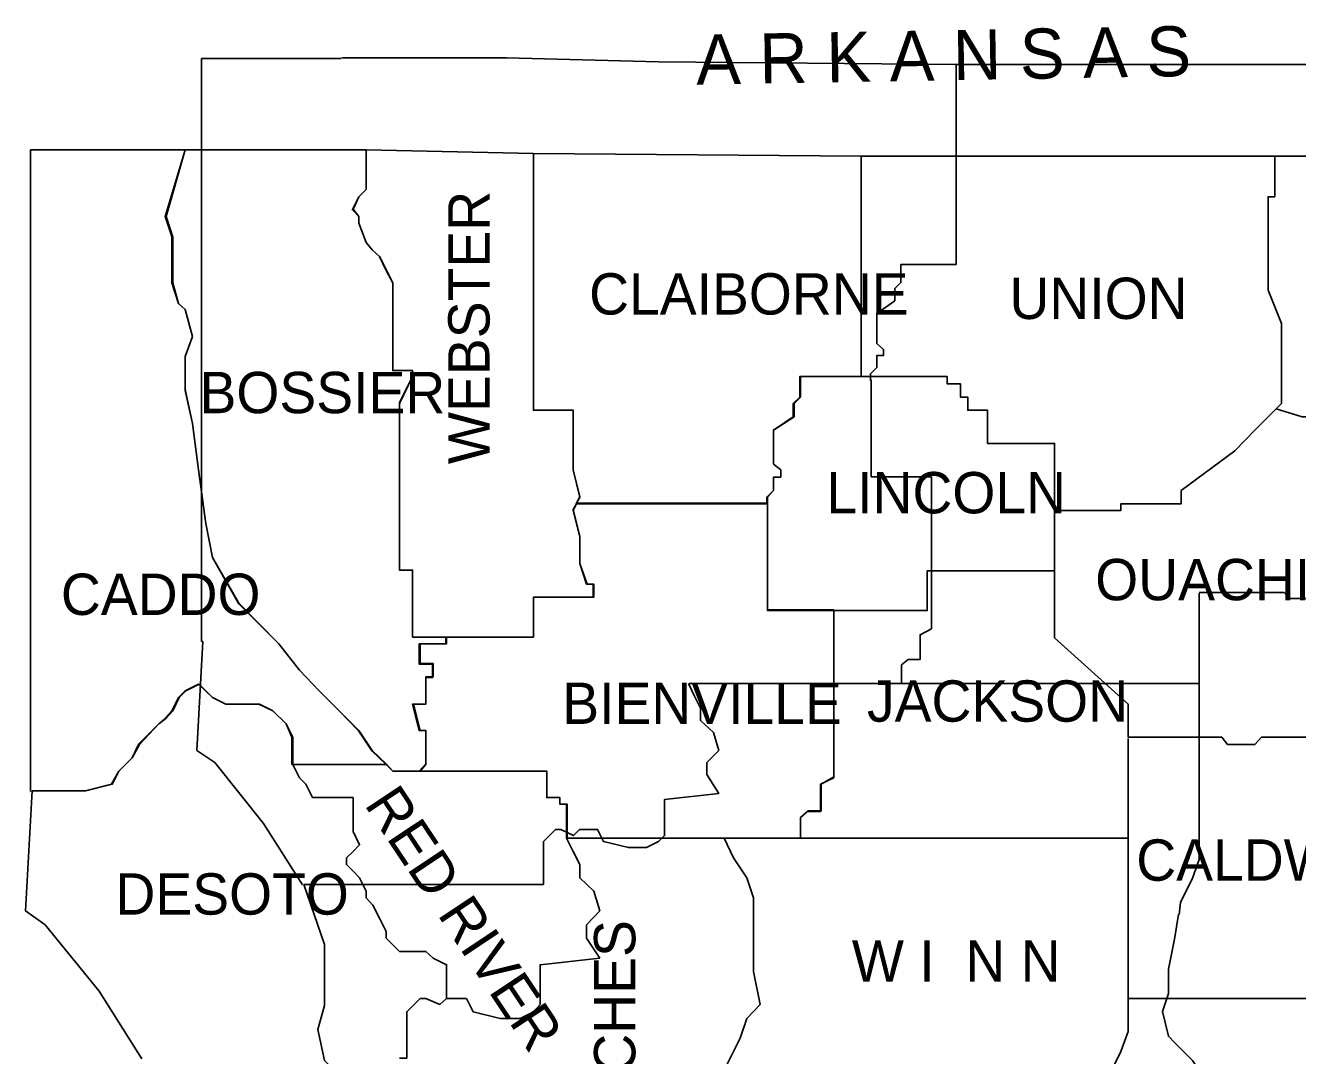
# Model space of a CAD drawing. Extents: x 0.19 to 2.82, y 0.04 to 1.79.
# Drawn here: x 2.194 to 2.3524, y 1.6264 to 1.7547 of the extents above; entities that cross this region are included whole.
import ezdxf

# ---------------------------------------------------------------- set-up
doc = ezdxf.new("R2010")
doc.units = 0
for name, color, linetype in [('Dist04', 7, 'Continuous'), ('Dist05', 7, 'Continuous'), ('Dist08', 7, 'Continuous'), ('Dist58', 7, 'Continuous'), ('Standard Info', 7, 'Continuous')]:
    doc.layers.add(name, color=color, linetype=linetype)

msp = doc.modelspace()

# ---------------------------------------------------------------- linework, layer by layer
at = {"layer": 'Dist04'}
for p, q in [((2.2159, 1.678), (2.2159, 1.75058)), ((2.2159, 1.75058), (2.23332, 1.75058)), ((2.2334, 1.75067), (2.2539, 1.75067)), ((2.2539, 1.75067), (2.27282, 1.75017)), ((2.27282, 1.75017), (2.3099, 1.74983)), ((2.21532, 1.66442), (2.21607, 1.678)), ((2.21607, 1.678), (2.2159, 1.678))]:
    msp.add_line(p, q, dxfattribs=at)
for points in [[(2.3099, 1.74983), (2.3099, 1.72492)], [(2.3099, 1.72492), (2.30299, 1.72492), (2.30299, 1.72267), (2.30224, 1.72192), (2.30224, 1.72042), (2.29999, 1.71883), (2.29999, 1.71508), (2.30082, 1.71433), (2.30082, 1.71358), (2.29999, 1.71358), (2.29999, 1.71208), (2.29924, 1.71133), (2.29924, 1.7105)], [(2.29932, 1.71058), (2.29932, 1.6985), (2.30682, 1.6985)], [(2.30682, 1.6985), (2.30682, 1.67958), (2.3054, 1.67883), (2.3054, 1.6765), (2.3054, 1.67575), (2.3039, 1.67575), (2.30307, 1.67508), (2.30307, 1.67275)], [(2.27657, 1.67275), (2.27732, 1.67117), (2.27807, 1.66967), (2.27807, 1.66817), (2.27965, 1.66667), (2.28032, 1.66442), (2.27882, 1.66292), (2.27882, 1.66142), (2.28032, 1.65908), (2.27357, 1.65833), (2.27357, 1.65383), (2.27282, 1.65308), (2.27132, 1.65233), (2.26907, 1.65233), (2.26599, 1.65308), (2.26524, 1.65458), (2.26299, 1.65458)], [(2.30307, 1.67275), (2.27665, 1.67275)], [(2.22849, 1.64767), (2.22365, 1.65533), (2.21757, 1.66292), (2.21532, 1.66442)], [(2.26299, 1.65458), (2.26224, 1.65383), (2.26065, 1.65458), (2.25999, 1.65458), (2.25849, 1.65308), (2.25849, 1.64775), (2.25765, 1.64775)], [(2.25765, 1.64775), (2.22865, 1.64775)]]:
    msp.add_lwpolyline(points, dxfattribs=at)
at = {"layer": 'Dist05'}
msp.add_line((2.3099, 1.74983), (2.35674, 1.74983), dxfattribs=at)
for points in [[(2.3099, 1.72492), (2.3099, 1.74983)], [(2.29924, 1.7105), (2.29924, 1.71133), (2.29999, 1.71208), (2.29999, 1.71358), (2.30082, 1.71358), (2.30082, 1.71433), (2.29999, 1.71508), (2.29999, 1.71883), (2.30224, 1.72042), (2.30224, 1.72192), (2.30299, 1.72267), (2.30299, 1.72492), (2.3099, 1.72492)], [(2.30682, 1.6985), (2.29932, 1.6985), (2.29932, 1.71058)], [(2.30307, 1.67275), (2.30307, 1.67508), (2.3039, 1.67575), (2.3054, 1.67575), (2.3054, 1.6765), (2.3054, 1.67883), (2.30682, 1.67958), (2.30682, 1.6985)], [(2.36049, 1.68408), (2.35524, 1.68408), (2.35449, 1.68333), (2.3514, 1.68333), (2.35074, 1.68408), (2.34015, 1.68408)], [(2.34015, 1.684), (2.34015, 1.67275)], [(2.34015, 1.67275), (2.30307, 1.67275)]]:
    msp.add_lwpolyline(points, dxfattribs=at)
at = {"layer": 'Dist08'}
for points in [[(2.27657, 1.67275), (2.27732, 1.67117), (2.27807, 1.66967), (2.27807, 1.66817), (2.27965, 1.66667), (2.28032, 1.66442), (2.27882, 1.66292), (2.27882, 1.66142), (2.28032, 1.65908), (2.27357, 1.65833), (2.27357, 1.65383), (2.27282, 1.65308), (2.27132, 1.65233), (2.26907, 1.65233), (2.26599, 1.65308), (2.26524, 1.65458), (2.26299, 1.65458)], [(2.30307, 1.67275), (2.27665, 1.67275)], [(2.34015, 1.67275), (2.30307, 1.67275)], [(2.34015, 1.65458), (2.34015, 1.67275)], [(2.26299, 1.65458), (2.26224, 1.65383), (2.26065, 1.65458), (2.25999, 1.65458), (2.25849, 1.65308), (2.25849, 1.64775), (2.25765, 1.64775)], [(2.33765, 1.644), (2.33782, 1.6455), (2.33932, 1.6485), (2.34015, 1.65083), (2.34015, 1.65458)], [(2.22865, 1.64775), (2.23124, 1.64025), (2.23124, 1.63267), (2.2304, 1.62967), (2.23124, 1.62583), (2.23199, 1.62508), (2.23649, 1.62283), (2.23882, 1.61675), (2.24032, 1.61375), (2.24182, 1.61), (2.24182, 1.60542), (2.24257, 1.60317), (2.24482, 1.60008), (2.24782, 1.59633), (2.24957, 1.59408)], [(2.25765, 1.64775), (2.22865, 1.64775)], [(2.36207, 1.60008), (2.36132, 1.60167), (2.35982, 1.60392), (2.35749, 1.60542), (2.35524, 1.60617), (2.35299, 1.6085), (2.3514, 1.61225), (2.3499, 1.61525), (2.3469, 1.61675), (2.3439, 1.61908), (2.34165, 1.62133), (2.34082, 1.62358), (2.33932, 1.62583), (2.33707, 1.62808), (2.33632, 1.62883), (2.33557, 1.63192), (2.33632, 1.63417), (2.33632, 1.63717), (2.33707, 1.64092), (2.33757, 1.644)]]:
    msp.add_lwpolyline(points, dxfattribs=at)
at = {"layer": 'Dist58'}
for points in [[(2.34015, 1.68408), (2.35074, 1.68408), (2.3514, 1.68333), (2.35449, 1.68333), (2.35524, 1.68408), (2.36049, 1.68408)], [(2.34015, 1.67275), (2.34015, 1.684)], [(2.34015, 1.65458), (2.34015, 1.67275)], [(2.33765, 1.644), (2.33782, 1.6455), (2.33932, 1.6485), (2.34015, 1.65083), (2.34015, 1.65458)], [(2.36207, 1.60008), (2.36132, 1.60167), (2.35982, 1.60392), (2.35749, 1.60542), (2.35524, 1.60617), (2.35299, 1.6085), (2.3514, 1.61225), (2.3499, 1.61525), (2.3469, 1.61675), (2.3439, 1.61908), (2.34165, 1.62133), (2.34082, 1.62358), (2.33932, 1.62583), (2.33707, 1.62808), (2.33632, 1.62883), (2.33557, 1.63192), (2.33632, 1.63417), (2.33632, 1.63717), (2.33707, 1.64092), (2.33757, 1.644)]]:
    msp.add_lwpolyline(points, dxfattribs=at)
at = {"layer": 'Standard Info'}
for p, q in [((2.19464, 1.65929), (2.19464, 1.73922)), ((2.19464, 1.73922), (2.2138, 1.73922)), ((2.2138, 1.73922), (2.21389, 1.73922)), ((2.21389, 1.73922), (2.23644, 1.73922)), ((2.23644, 1.73922), (2.25725, 1.73876)), ((2.25725, 1.73876), (2.29804, 1.7384)), ((2.29804, 1.7384), (2.34955, 1.7384)), ((2.34955, 1.7384), (2.39951, 1.7384)), ((2.34974, 1.70696), (2.35038, 1.7076)), ((2.2622, 1.6944), (2.26265, 1.69522)), ((2.24634, 1.67854), (2.24221, 1.67854)), ((2.22727, 1.66268), (2.23891, 1.66268)), ((2.23974, 1.66186), (2.23891, 1.66277)), ((2.24304, 1.66186), (2.23974, 1.66186)), ((2.194, 1.64444), (2.19482, 1.65938))]:
    msp.add_line(p, q, dxfattribs=at)
for points in [[(2.21389, 1.73922), (2.21141, 1.73088), (2.21224, 1.72841), (2.21224, 1.72511), (2.21224, 1.72263), (2.21306, 1.72006), (2.21389, 1.71933), (2.2148, 1.71594), (2.21389, 1.71346), (2.21389, 1.70925), (2.2148, 1.70512), (2.21554, 1.69935), (2.21645, 1.69266), (2.21728, 1.68844), (2.22058, 1.68266), (2.22553, 1.67771), (2.2281, 1.67441), (2.23057, 1.67185), (2.23305, 1.66937), (2.23552, 1.66681), (2.23717, 1.66433), (2.23891, 1.66268), (2.22718, 1.66268), (2.22718, 1.66351), (2.22718, 1.66607), (2.22645, 1.66772), (2.2248, 1.66937), (2.22305, 1.6702), (2.22058, 1.6702), (2.21893, 1.6702), (2.21728, 1.67102), (2.21554, 1.67267), (2.21554, 1.67267), (2.21389, 1.67185), (2.21306, 1.67102), (2.21224, 1.66937), (2.21141, 1.66846), (2.21059, 1.66772), (2.20811, 1.66525), (2.20729, 1.66351), (2.20564, 1.66186), (2.20472, 1.66021), (2.20142, 1.65938), (2.19895, 1.65938), (2.19482, 1.65938)], [(2.23891, 1.66277), (2.23717, 1.66442), (2.23552, 1.6669), (2.23305, 1.66937), (2.23057, 1.67185), (2.2281, 1.67441), (2.22553, 1.67771), (2.22058, 1.68276), (2.21728, 1.68844), (2.21645, 1.69266), (2.21554, 1.69935), (2.2148, 1.70512), (2.21389, 1.70934), (2.21389, 1.71346), (2.2148, 1.71594), (2.21389, 1.71933), (2.21306, 1.72006), (2.21233, 1.72263), (2.21233, 1.72511), (2.21233, 1.72831), (2.2115, 1.73088), (2.21389, 1.73922)], [(2.23644, 1.73922), (2.23644, 1.73427), (2.23552, 1.73336), (2.2347, 1.73171), (2.23552, 1.73088), (2.23552, 1.73006), (2.23644, 1.72767), (2.23717, 1.72676), (2.23809, 1.72593), (2.23891, 1.72419), (2.23974, 1.72263), (2.23974, 1.72006), (2.23974, 1.71676), (2.23974, 1.71502), (2.23974, 1.71429), (2.23974, 1.71264), (2.23974, 1.71172), (2.24221, 1.71172), (2.24221, 1.71099), (2.24056, 1.70769), (2.24056, 1.68688), (2.24221, 1.68688), (2.24221, 1.67854), (2.24634, 1.67854), (2.24634, 1.67771), (2.24304, 1.67771), (2.24304, 1.67515), (2.24469, 1.67515), (2.24469, 1.6735), (2.24386, 1.6735), (2.24386, 1.6702), (2.24221, 1.6702), (2.24304, 1.6669), (2.24386, 1.6669), (2.24386, 1.66525), (2.24386, 1.6636), (2.24386, 1.66277), (2.24304, 1.66186)], [(2.24221, 1.67854), (2.24221, 1.68688), (2.24056, 1.68688), (2.24056, 1.7076), (2.24221, 1.71099), (2.24221, 1.71172), (2.23974, 1.71172), (2.23974, 1.71264), (2.23974, 1.71429), (2.23974, 1.71511), (2.23974, 1.71676), (2.23974, 1.72006), (2.23974, 1.72263), (2.23891, 1.72428), (2.23809, 1.72593), (2.23717, 1.72676), (2.23644, 1.72767), (2.23552, 1.73006), (2.23552, 1.73088), (2.23479, 1.7318), (2.23552, 1.73336), (2.23644, 1.73427), (2.23644, 1.73922)], [(2.25725, 1.73876), (2.25725, 1.70677), (2.2622, 1.70677), (2.2622, 1.70173), (2.2622, 1.69935), (2.26302, 1.69605), (2.2622, 1.69431), (2.26302, 1.69101), (2.26302, 1.68771), (2.26385, 1.68514), (2.26467, 1.68514), (2.26467, 1.68349), (2.25725, 1.68349), (2.25725, 1.67854), (2.24634, 1.67854)], [(2.26256, 1.69513), (2.26302, 1.69596), (2.2622, 1.69935), (2.2622, 1.70173), (2.2622, 1.70677), (2.25725, 1.70677), (2.25725, 1.73876)], [(2.29804, 1.7384), (2.29804, 1.71099)], [(2.29804, 1.71099), (2.29804, 1.7384)], [(2.34955, 1.7384), (2.34955, 1.73336), (2.34873, 1.73336), (2.34873, 1.73088), (2.34873, 1.72171), (2.35038, 1.71759), (2.35038, 1.71429), (2.35038, 1.71099), (2.35038, 1.7076), (2.34955, 1.70677), (2.34708, 1.7043), (2.3446, 1.70173), (2.33791, 1.69678), (2.33791, 1.69513), (2.3304, 1.69513), (2.3304, 1.69431), (2.32215, 1.69431)], [(2.35038, 1.7076), (2.35038, 1.71099), (2.35038, 1.71429), (2.35038, 1.71759), (2.34873, 1.72171), (2.34873, 1.73088), (2.34873, 1.73336), (2.34955, 1.73336), (2.34955, 1.7384)], [(2.29804, 1.71099), (2.29043, 1.71099), (2.29043, 1.70842), (2.2896, 1.7076), (2.2896, 1.70595), (2.28713, 1.7043), (2.28713, 1.70008), (2.28805, 1.69935), (2.28805, 1.69843), (2.28713, 1.69843), (2.28713, 1.69678), (2.2863, 1.69596), (2.2863, 1.69513)], [(2.2864, 1.69513), (2.2864, 1.69596), (2.28713, 1.69678), (2.28713, 1.69843), (2.28805, 1.69843), (2.28805, 1.69935), (2.28713, 1.70008), (2.28713, 1.7043), (2.2897, 1.70595), (2.2897, 1.7076), (2.29052, 1.70842), (2.29052, 1.71099), (2.29804, 1.71099)], [(2.2864, 1.69513), (2.2864, 1.69596), (2.28713, 1.69678), (2.28713, 1.69843), (2.28805, 1.69843), (2.28805, 1.69935), (2.28713, 1.70008), (2.28713, 1.7043), (2.2897, 1.70595), (2.2897, 1.7076), (2.29052, 1.70842), (2.29052, 1.71099), (2.29804, 1.71099)], [(2.32215, 1.69431), (2.32215, 1.70265), (2.3138, 1.70265), (2.3138, 1.70677), (2.31133, 1.70677), (2.31133, 1.70842), (2.31041, 1.70842), (2.31041, 1.71007), (2.30876, 1.71007), (2.30876, 1.71099), (2.29804, 1.71099)], [(2.29804, 1.71099), (2.30876, 1.71099), (2.30876, 1.71007), (2.31041, 1.71007), (2.31041, 1.70842), (2.31133, 1.70842), (2.31133, 1.70677), (2.3138, 1.70677), (2.3138, 1.70265), (2.32215, 1.70265), (2.32215, 1.69431), (2.32215, 1.68679)], [(2.32215, 1.69431), (2.3304, 1.69431), (2.3304, 1.69513), (2.33791, 1.69513), (2.33791, 1.69678), (2.3446, 1.70173), (2.34708, 1.7043), (2.34974, 1.70696)], [(2.34974, 1.70696), (2.35295, 1.70595), (2.35625, 1.70595), (2.3579, 1.7043), (2.35955, 1.70265), (2.36202, 1.70265), (2.36285, 1.70173), (2.36202, 1.701), (2.3612, 1.70008), (2.3612, 1.69678), (2.35955, 1.69678), (2.35955, 1.69348), (2.3612, 1.69348), (2.36285, 1.69009), (2.36285, 1.68761), (2.3612, 1.68596), (2.35955, 1.68596), (2.35955, 1.68266), (2.35872, 1.68266), (2.35872, 1.68101), (2.3546, 1.67597), (2.3546, 1.6702), (2.35368, 1.6702), (2.35368, 1.66607)], [(2.36285, 1.69009), (2.3612, 1.69348), (2.35955, 1.69348), (2.35955, 1.69678), (2.3612, 1.69678), (2.3612, 1.70008), (2.36202, 1.701), (2.36285, 1.70173), (2.36202, 1.70265), (2.35955, 1.70265), (2.3579, 1.7043), (2.35625, 1.70595), (2.35295, 1.70595), (2.34974, 1.70696)], [(2.2863, 1.69513), (2.26256, 1.69513)], [(2.26265, 1.69522), (2.2864, 1.69522)], [(2.2864, 1.69522), (2.2864, 1.68193), (2.29465, 1.68193)], [(2.29465, 1.68184), (2.2864, 1.68184), (2.2864, 1.69513)], [(2.24643, 1.67854), (2.25725, 1.67854), (2.25725, 1.68349), (2.26476, 1.68349), (2.26476, 1.68514), (2.26394, 1.68514), (2.26302, 1.68771), (2.26302, 1.6911), (2.2622, 1.6944)], [(2.33131, 1.66607), (2.33131, 1.6702), (2.32215, 1.67845), (2.32215, 1.68679), (2.32215, 1.69431)], [(2.32215, 1.68679), (2.30629, 1.68679), (2.30629, 1.68184), (2.29465, 1.68184)], [(2.29465, 1.68184), (2.30629, 1.68184), (2.30629, 1.68679), (2.32215, 1.68679)], [(2.32215, 1.68679), (2.32215, 1.67845), (2.33131, 1.6702), (2.33131, 1.66607)], [(2.29465, 1.68193), (2.29465, 1.66112), (2.29309, 1.66021), (2.29309, 1.65773), (2.29309, 1.65691), (2.29144, 1.65691), (2.29052, 1.65608), (2.29052, 1.65351)], [(2.29052, 1.65351), (2.29052, 1.65608), (2.29135, 1.65681), (2.293, 1.65681), (2.293, 1.65773), (2.293, 1.66021), (2.29465, 1.66103), (2.29465, 1.68184)], [(2.24313, 1.66186), (2.24386, 1.66268), (2.24386, 1.6636), (2.24386, 1.66525), (2.24386, 1.6669), (2.24313, 1.6669), (2.2423, 1.6702), (2.24386, 1.6702), (2.24386, 1.67359), (2.24478, 1.67359), (2.24478, 1.67524), (2.24313, 1.67524), (2.24313, 1.67771), (2.24643, 1.67771), (2.24643, 1.67854)], [(2.19482, 1.65938), (2.19895, 1.65938), (2.20151, 1.65938), (2.20481, 1.66021), (2.20564, 1.66186), (2.20729, 1.66351), (2.2082, 1.66516), (2.21059, 1.66772), (2.2115, 1.66846), (2.21233, 1.66937), (2.21315, 1.67102), (2.21398, 1.67185), (2.21563, 1.67267), (2.21563, 1.67267), (2.21728, 1.67102), (2.21893, 1.6702), (2.22058, 1.6702), (2.22315, 1.6702), (2.2248, 1.66937), (2.22645, 1.66772), (2.22727, 1.66607), (2.22727, 1.66351), (2.22727, 1.66268)], [(2.35368, 1.66607), (2.3479, 1.66607), (2.34708, 1.66516), (2.34369, 1.66516), (2.34295, 1.66607), (2.33131, 1.66607)], [(2.33131, 1.66607), (2.34295, 1.66607), (2.34369, 1.66516), (2.34708, 1.66516), (2.3479, 1.66607), (2.35625, 1.66607), (2.35625, 1.66516), (2.35542, 1.66268), (2.35625, 1.66186), (2.35625, 1.66021), (2.35707, 1.65938), (2.3579, 1.65773), (2.35872, 1.65681), (2.36037, 1.65608), (2.36202, 1.65608), (2.36367, 1.65608)], [(2.33131, 1.66589), (2.33131, 1.65351)], [(2.33131, 1.65351), (2.33131, 1.6658)], [(2.22727, 1.66268), (2.2281, 1.66103), (2.22892, 1.66021), (2.22975, 1.65856), (2.23479, 1.65856), (2.23479, 1.65434), (2.23561, 1.65269), (2.23479, 1.65186), (2.23396, 1.65104), (2.23396, 1.65021), (2.23479, 1.64939), (2.23561, 1.64856), (2.23644, 1.64691), (2.23644, 1.64609), (2.23726, 1.64517), (2.23809, 1.64352), (2.23891, 1.64187), (2.23891, 1.64105), (2.23974, 1.64022), (2.24056, 1.6394), (2.24221, 1.6394), (2.24386, 1.6394), (2.24478, 1.63857), (2.24643, 1.63775), (2.24643, 1.63353)], [(2.24643, 1.63353), (2.24643, 1.63775), (2.24478, 1.63857), (2.24386, 1.6394), (2.24221, 1.6394), (2.24056, 1.6394), (2.23974, 1.64022), (2.23891, 1.64105), (2.23891, 1.64187), (2.23809, 1.64352), (2.23726, 1.64517), (2.23644, 1.64609), (2.23644, 1.64691), (2.23561, 1.64856), (2.23479, 1.64939), (2.23396, 1.65021), (2.23396, 1.65104), (2.23479, 1.65186), (2.23561, 1.65269), (2.23479, 1.65434), (2.23479, 1.65856), (2.22975, 1.65856), (2.22892, 1.66021), (2.2281, 1.66103), (2.22727, 1.66268)], [(2.23891, 1.66268), (2.23974, 1.66186), (2.2589, 1.66186), (2.2589, 1.65856), (2.26055, 1.65856), (2.26055, 1.65773), (2.26137, 1.65773), (2.26137, 1.65351)], [(2.26146, 1.65351), (2.26146, 1.65773), (2.26055, 1.65773), (2.26055, 1.65856), (2.2589, 1.65856), (2.2589, 1.66186), (2.24313, 1.66186)], [(2.24056, 1.62611), (2.24148, 1.62611), (2.24148, 1.63188), (2.24313, 1.63353), (2.24386, 1.63353), (2.2456, 1.6328), (2.24643, 1.63353), (2.2489, 1.63353), (2.24973, 1.63188), (2.25312, 1.63106), (2.2556, 1.63106), (2.25725, 1.63188), (2.25807, 1.6328), (2.25807, 1.63775), (2.2655, 1.63857), (2.26385, 1.64105), (2.26385, 1.6427), (2.2655, 1.64444), (2.26476, 1.64691), (2.26302, 1.64856), (2.26302, 1.65021), (2.2622, 1.65186), (2.26137, 1.65351)], [(2.26137, 1.65351), (2.2622, 1.65186), (2.26302, 1.65021), (2.26302, 1.64856), (2.26476, 1.64691), (2.2655, 1.64444), (2.26385, 1.6427), (2.26385, 1.64105), (2.2655, 1.63857), (2.25807, 1.63775), (2.25807, 1.6328), (2.25725, 1.63188), (2.2556, 1.63106), (2.25312, 1.63106), (2.24973, 1.63188), (2.2489, 1.63353), (2.24643, 1.63353)], [(2.26137, 1.65351), (2.28099, 1.65351)], [(2.29052, 1.65351), (2.26146, 1.65351)], [(2.27888, 1.61364), (2.27888, 1.61941), (2.2797, 1.62024), (2.2797, 1.62106), (2.2797, 1.62281), (2.28053, 1.62528), (2.28135, 1.62528), (2.28218, 1.62693), (2.283, 1.62858), (2.28383, 1.63106), (2.28548, 1.6328), (2.28465, 1.63692), (2.28465, 1.64105), (2.28465, 1.64352), (2.28465, 1.64609), (2.28383, 1.64856), (2.28218, 1.65104), (2.28099, 1.65351)], [(2.28099, 1.65351), (2.33131, 1.65351)], [(2.28099, 1.65351), (2.28218, 1.65104), (2.28383, 1.64856), (2.28465, 1.64609), (2.28465, 1.64352), (2.28465, 1.64105), (2.28465, 1.63692), (2.28548, 1.6328), (2.28383, 1.63106), (2.283, 1.62858), (2.28218, 1.62693), (2.28135, 1.62528)], [(2.33131, 1.65351), (2.29052, 1.65351)], [(2.33131, 1.65351), (2.33131, 1.62941), (2.3304, 1.62693), (2.32875, 1.62354), (2.32865, 1.62308)], [(2.33131, 1.63353), (2.33131, 1.65351)], [(2.20848, 1.62601), (2.20316, 1.63445), (2.19647, 1.6427), (2.194, 1.64444)], [(2.36459, 1.63775), (2.36202, 1.63775), (2.36285, 1.63353), (2.35542, 1.63353), (2.33131, 1.63353)], [(2.24643, 1.63353), (2.2456, 1.6328), (2.24386, 1.63353), (2.24313, 1.63353), (2.24148, 1.63188), (2.24148, 1.62611), (2.24056, 1.62611)], [(2.32856, 1.62189), (2.32875, 1.62354), (2.3304, 1.62693), (2.33131, 1.62941), (2.33131, 1.63353)], [(2.33131, 1.63353), (2.35542, 1.63353)]]:
    msp.add_lwpolyline(points, dxfattribs=at)

# ---------------------------------------------------------------- texts
for s, height, rotation, p in [('A R K A N S A S', 0.0062368, 1.0059, (2.27755, 1.74731)), ('WEBSTER', 0.005147, 90, (2.25179, 1.70006)), ('RED RIVER', 0.005147, 303.6501, (2.2361, 1.6577)), ('NATCHITOCHES', 0.0051469, 90, (2.26994, 1.589))]:
    msp.add_text(s, height=height, rotation=rotation, dxfattribs=at).set_placement(p)
for s, p in [('CLAIBORNE', (2.26418, 1.71869)), ('UNION', (2.31652, 1.71814)), ('BOSSIER', (2.21567, 1.70641)), ('LINCOLN', (2.29373, 1.69394)), ('OUACHITA', (2.3272, 1.68312)), ('CADDO', (2.19841, 1.68129)), ('BIENVILLE', (2.26084, 1.66772)), ('JACKSON', (2.29878, 1.668)), ('CALDWELL', (2.33231, 1.6482)), ('DESOTO', (2.2052, 1.64398)), ('W I  N N', (2.29689, 1.63564))]:
    msp.add_text(s, height=0.005147, dxfattribs=at).set_placement(p)

doc.saveas('drawing.dxf')
